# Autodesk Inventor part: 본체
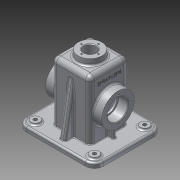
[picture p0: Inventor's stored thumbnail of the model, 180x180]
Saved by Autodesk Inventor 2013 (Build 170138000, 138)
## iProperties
Created: 2016-06
Part Number: 본체
Material: 알루미늄 6061
Document SubType Name: Modeling
Designer: k
Density: 2.71 g/cm^3
Mass: 862.386 g
Surface Area: 914.898 cm^2
Volume: 318.223 cm^3
Author: k
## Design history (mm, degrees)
sketch "스케치1"
  geometry: L1 (-32.5, 32.5)-(32.5, 32.5); L2 (32.5, 32.5)-(32.5, -32.5); L3 (32.5, -32.5)-(-32.5, -32.5); L4 (-32.5, -32.5)-(-32.5, 32.5); 2 further points
  constraints: 8 end point, 2 parallel, 1 coincident, 1 horizontal, 1 perpendicular
  dimensions: "d0" = 65 distance of L2.end L3.end; "d1" = 65 distance of L1.end L2.end
extrude "돌출1" new body sketch "스케치1" distance "d2" = 110; taper "d3" = 0 deg
sketch "스케치2"
  geometry: L1 (-65, 57.5)-(65, 57.5); L2 (65, 57.5)-(65, -57.5); L3 (65, -57.5)-(-65, -57.5); L4 (-65, -57.5)-(-65, 57.5); L5 (-65, 57.5)-(65, -57.5); L6 (65, 57.5)-(-65, -57.5); 1 further point
  constraints: 12 end point, 2 midpoint, 2 parallel, 1 horizontal, 1 perpendicular
  dimensions: "d4" = 130 distance of L2.end L3.end; "d5" = 115 distance of L1.end L2.end
extrude "돌출2" join sketch "스케치2" distance "d6" = 10; taper "d7" = 0 deg
feature "쉘1" dims "d8" = 12, "d9" = 5
sketch "스케치4"
  geometry: L1 (-110, -25)-(-110, 90) reference; C1 r 27.5 at (-55, 32.5); 2 further points
  constraints: 1 centre point, 1 horizontal alignment, 1 midpoint
  dimensions: "d22" = 55 diameter of C1; "d24" = 55 distance from line of C1.centre L1
fillet "모깎기1" dims "d25" = 8
fillet "모깎기2" dims "d26" = 8
extrude "돌출4" join sketch "스케치4" distance "d27" = 15; taper "d28" = 0 deg
fillet "모깎기3" dims "d29" = 15
node "작업 평면1"
sketch "스케치5"
  geometry: C1 r 20 at (0, 0); 1 further point
  constraints: 1 centre point, 1 coincident
  dimensions: "d31" = 40 diameter of C1
extrude "돌출5" join sketch "스케치5" distance "d32" = 15; taper "d33" = 5 deg
sketch "스케치6"
  geometry: L1 (27.5, 0)-(27.5, 105) reference; L2 (27.5, 105)-(-27.5, 105) reference; L3 (-27.5, 105)-(-27.5, 0) reference; L4 (-27.5, 0)-(-57.5, 0) reference; L5 (-57.5, 0)-(-57.5, 10) reference; L6 (-57.5, 10)-(-32.5, 10) reference; L7 (-32.5, 10)-(-32.5, 102) reference; L8 (-24.5, 110)-(-20.875, 110) reference; L9 (-20.875, 110)-(-20, 120) reference; L10 (-20, 120)-(20, 120) reference; L11 (20, 120)-(20.875, 110) reference; L12 (20.875, 110)-(24.5, 110) reference; L13 (32.5, 102)-(32.5, 10) reference; L14 (32.5, 10)-(57.5, 10) reference; L15 (57.5, 10)-(57.5, 0) reference; L16 (57.5, 0)-(27.5, 0) reference; L17 (47.5, 10)-(32.5, 95.069); A1 r 8 centre (-24.5, 102) between (-24.5, 110) and (-32.5, 102) reference; A2 r 8 centre (24.5, 102) between (32.5, 102) and (24.5, 110) reference; 1 further point
  constraints: 2 end point, 2 point on line
  dimensions: "d34" = 10 distance from line of L15 L17.start; "d35" = 10 deg angle of L15 L17
feature "리브1" sketch "스케치6" dims "d36" = 1, "d37" = 10, "d38" = 0, "d39" = 0, "d40" = 1, "d41" = 1
sketch "스케치7"
  geometry: L1 (-42.5, 12)-(-42.5, 27.5); L2 (-27.5, 0)-(-27.5, 105) reference; 1 further point
  constraints: 2 end point, 1 vertical
  dimensions: "d42" = 15 distance between parallel lines of L1 L2
feature "리브2" sketch "스케치7" dims "d43" = 1, "d44" = 6, "d45" = 0, "d46" = 0, "d47" = 1, "d48" = 1
hole "구멍2" diameter "d51" = 21; stored, may be unused: countersink angle "d55" = 90 deg, drill point angle "d57" = 118 deg; dims "d49" = 10, "d50" = 10, "d52" = 6, "d53" = 35, "d54" = 17, "d56" = 8
hole "구멍3" diameter "d60" = 30; stored, may be unused: countersink angle "d64" = 90 deg, drill point angle "d66" = 118 deg; dims "d58" = 10, "d59" = 10, "d61" = 6, "d62" = 35, "d63" = 17, "d65" = 8
sketch "스케치8"
  geometry: L1 (-65, 42.5)-(-65, -42.5) reference; L2 (-50, -57.5)-(50, -57.5) reference; L3 (65, -42.5)-(65, 42.5) reference; L4 (50, 57.5)-(-50, 57.5) reference; L5 (-50, 52.5)-(50, 52.5); L6 (60, 42.5)-(60, -42.5); L7 (50, -52.5)-(-50, -52.5); L8 (-60, -42.5)-(-60, 42.5); A1 r 15 centre (-50, -42.5) between (-65, -42.5) and (-50, -57.5) reference; A2 r 15 centre (50, -42.5) between (50, -57.5) and (65, -42.5) reference; A3 r 15 centre (50, 42.5) between (65, 42.5) and (50, 57.5) reference; A4 r 15 centre (-50, 42.5) between (-50, 57.5) and (-65, 42.5) reference; A5 r 10 centre (50, 42.5) between (60, 42.5) and (50, 52.5); A6 r 10 centre (50, -42.5) between (50, -52.5) and (60, -42.5); A7 r 10 centre (-50, -42.5) between (-60, -42.5) and (-50, -52.5); A8 r 10 centre (-50, 42.5) between (-50, 52.5) and (-60, 42.5); 1 further point
  constraints: 8 end point, 8 point on circle, 4 centre point, 7 other
  dimensions: "d67" = 5 distance between parallel lines of L5 L4
extrude "돌출6" cut sketch "스케치8" distance "d68" = 2; taper "d69" = 0 deg
sketch "스케치9"
  geometry: C1 r 7.5 at (-50, 42.5); C2 r 7.5 at (50, 42.5); C3 r 7.5 at (50, -42.5); C4 r 7.5 at (-50, -42.5); A1 r 15 centre (50, 42.5) between (65, 42.5) and (50, 57.5) reference; A2 r 15 centre (-50, 42.5) between (-50, 57.5) and (-65, 42.5) reference; A3 r 15 centre (-50, -42.5) between (-65, -42.5) and (-50, -57.5) reference; A4 r 15 centre (50, -42.5) between (50, -57.5) and (65, -42.5) reference; 1 further point
  constraints: 4 centre point, 4 coincident, 2 equal radius, 1 vertical alignment
  dimensions: "d70" = 15 diameter of C1; "d71" = 15 diameter of C4
extrude "돌출7" join sketch "스케치9" distance "d72" = 3; taper "d73" = 0 deg
hole "구멍4" diameter "d76" = 6; stored, may be unused: countersink angle "d80" = 90 deg, drill point angle "d82" = 118 deg; dims "d74" = 10, "d75" = 10, "d77" = 6, "d78" = 35, "d79" = 17, "d81" = 8
hole "구멍5" diameter "d85" = 6; stored, may be unused: countersink angle "d89" = 90 deg, drill point angle "d91" = 118 deg; dims "d83" = 10, "d84" = 10, "d86" = 6, "d87" = 35, "d88" = 17, "d90" = 8
hole "구멍6" diameter "d94" = 6; stored, may be unused: countersink angle "d98" = 90 deg, drill point angle "d100" = 118 deg; dims "d92" = 10, "d93" = 10, "d95" = 6, "d96" = 35, "d97" = 17, "d99" = 8
hole "구멍7" diameter "d103" = 6; stored, may be unused: countersink angle "d107" = 90 deg, drill point angle "d109" = 118 deg; dims "d101" = 10, "d102" = 10, "d104" = 6, "d105" = 35, "d106" = 17, "d108" = 8
fillet "모깎기4" dims "d110" = 3
fillet "모깎기5" dims "d111" = 3
fillet "모깎기6" dims "d112" = 3
fillet "모깎기7" dims "d113" = 3
fillet "모깎기8" dims "d114" = 3
fillet "모깎기9" dims "d115" = 3
fillet "모깎기10" dims "d116" = 3
fillet "모깎기11" dims "d117" = 3
fillet "모깎기12" dims "d118" = 3
fillet "모깎기13" dims "d119" = 3
fillet "모깎기14" dims "d120" = 3
sketch "스케치10"
  geometry: C1 r 17.5 at (0, 0) reference; 2 further points
  constraints: 1 horizontal alignment
  dimensions: "d121" = 21 distance of point (-21, 0) C1.centre
hole "구멍8" sketch "스케치10" at (-21, 0) diameter "d122" = 3.242; stored, may be unused: countersink angle "d126" = 90 deg, drill point angle "d128" = 118 deg; dims "d123" = 8, "d124" = 35, "d125" = 17, "d127" = 10
fillet "모깎기15" dims "d132" = 1
sketch "스케치11"
  geometry: C1 r 10.5 at (0, 0) reference; 1 further point
  constraints: 1 vertical alignment
  dimensions: "d133" = 14.5 distance of point (0, 14.5) C1.centre
hole "구멍9" sketch "스케치11" at (0, 14.5) diameter "d134" = 2.459; stored, may be unused: countersink angle "d138" = 90 deg, drill point angle "d140" = 118 deg; dims "d135" = 7, "d136" = 35, "d137" = 17, "d139" = 9
fillet "모깎기16" dims "d144" = 0.3
fillet "모깎기17" dims "d145" = 0.3
fillet "모깎기18" dims "d146" = 3
chamfer "모따기1" distance "d147" = 1; stored, may be unused: second distance "d148" = 2, angle "d149" = 45 deg
chamfer "모따기2" distance "d150" = 1; stored, may be unused: second distance "d151" = 2, angle "d152" = 45 deg
fillet "모깎기19" dims "d153" = 3
fillet "모깎기20" dims "d154" = 3
sketch "스케치12"
  geometry: L1 (-18, 4.5)-(-18, 44.5) reference; L2 (0, -8)-(91, -8) reference; 1 further point
  constraints: 1 other
  dimensions: "d155" = 26 distance from line of point (8, 24.5) L1; "d156" = 32.5 distance from line of point (8, 24.5) L2
feature "엠보싱1" sketch "스케치12" dims "d157" = 0.5, "d158" = 0
node "솔리드1"
mirror "대칭1"
mirror "대칭2"
mirror "대칭3"
mirror "대칭4"
pattern_circular "원형 패턴1" dims angle "d130" = 360 deg
mirror "대칭5"
pattern_circular "원형 패턴2" dims angle "d142" = 360 deg
node "절단 모서리 투영1"
